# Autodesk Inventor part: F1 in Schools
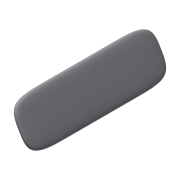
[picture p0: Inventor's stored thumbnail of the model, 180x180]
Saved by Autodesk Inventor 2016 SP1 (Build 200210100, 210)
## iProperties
Created: 2015-12
Part Number: F1 in Schools
Material: Generic
Document SubType Name: Modeling
Designer: Autodesk Inc.
Density: 1 g/cm^3
Appearance: Default
Author: Autodesk Inc
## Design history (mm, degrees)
feature "Form1"
body "Solid1"
